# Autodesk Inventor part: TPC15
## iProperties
Shininess: 64.0
Length Units: 11272
Angle Units: 11279
Time Units: 11290
Mass Units: 11286
Length Display Precision: 3
Angle Display Precision: 2
Compacted: True
Part Number: TPC15
Document SubType Name: Modeling
Created: 2004-08
Designer: Lori
Manufacturer: Standard
Standards Organization: Custom
Material: Stainless Steel, 440C
Density: 0.0
Volumn: 0.0
Area: 0.0
PropertySet Name: Model Information
Control State: 0
Master: False
Checked Out: False
Author: Lori
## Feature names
1. Base1
